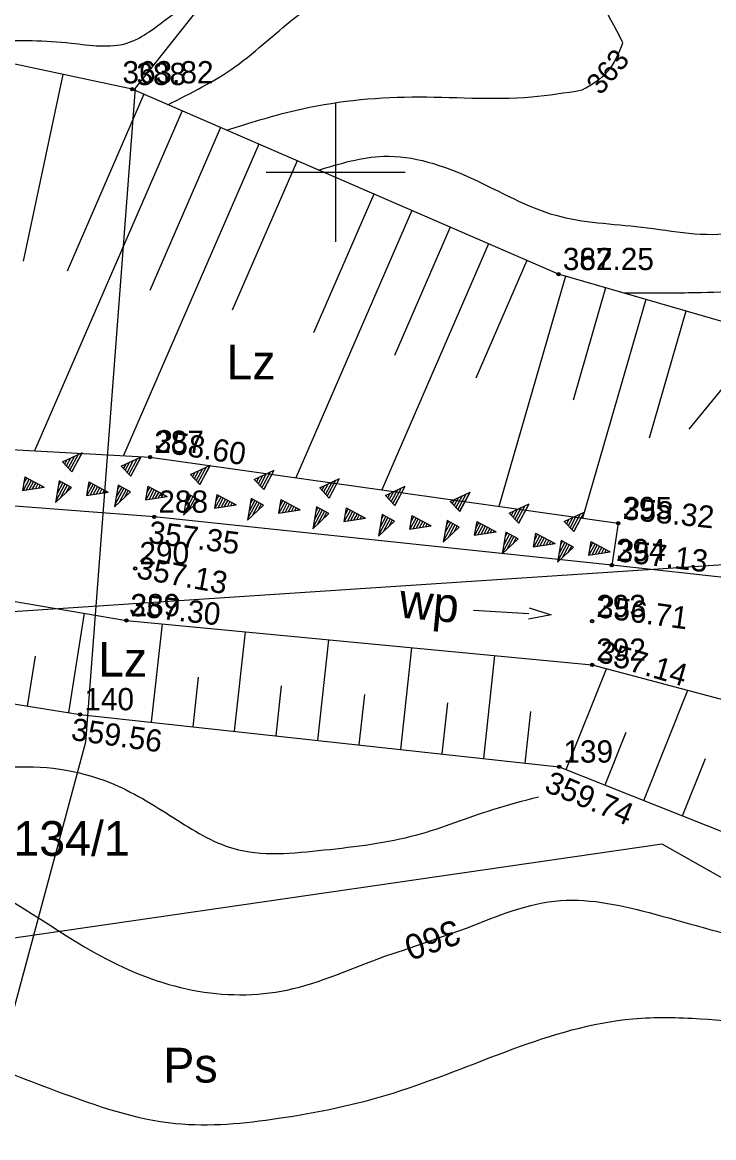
# Model space of a CAD drawing. Extents: x 4635329 to 4651863, y 5356628 to 5367582.
# Drawn here: x 4651688.74 to 4651713.58, y 5357115.3 to 5357155.39 of the extents above; entities that cross this region are included whole.
import ezdxf

# ---------------------------------------------------------------- set-up
doc = ezdxf.new("R2010")
doc.units = 0
for name, color, linetype in [('Level 12', 7, 'Continuous'), ('Level 2', 7, 'Continuous'), ('Level 4', 7, 'Continuous'), ('Level 44', 7, 'Continuous'), ('Level 45', 7, 'Continuous'), ('Level 46', 7, 'Continuous'), ('Level 47', 7, 'Continuous'), ('Level 48', 7, 'Continuous'), ('Level 49', 7, 'Continuous'), ('Level 5', 7, 'Continuous'), ('Level 50', 7, 'Continuous'), ('Level 51', 7, 'Continuous'), ('Level 60', 7, 'Continuous'), ('Level 63', 7, 'Continuous')]:
    doc.layers.add(name, color=color, linetype=linetype)

msp = doc.modelspace()

# ---------------------------------------------------------------- linework, layer by layer
at = {"layer": 'Level 2'}
for p, q in [((4651703.566, 5357166.6), (4651692.792, 5357153.016)), ((4651692.792, 5357153.016), (4651691.014, 5357129.514)), ((4651691.014, 5357129.514), (4651683.746, 5357102.537))]:
    msp.add_line(p, q, dxfattribs=at)
at = {"layer": 'Level 4'}
for p, q in [((4651676.592, 5357133.424), (4651715.978, 5357136.035)), ((4651711.734, 5357125.845), (4651674.589, 5357120.47)), ((4651726.932, 5357117.207), (4651711.734, 5357125.845))]:
    msp.add_line(p, q, dxfattribs=at)
at = {"layer": 'Level 44'}
for centre in [(4651692.69, 5357152.98), (4651708.01, 5357146.33), (4651693.33, 5357139.76), (4651693.48, 5357137.61), (4651710.15, 5357137.38), (4651692.8, 5357135.76), (4651709.92, 5357135.87), (4651692.48, 5357133.89), (4651709.21, 5357133.86), (4651709.21, 5357132.29), (4651690.82, 5357130.51), (4651708.03, 5357128.63)]:
    msp.add_circle(centre, 0.04, dxfattribs=at)
at = {"layer": 'Level 46'}
msp.add_line((4651702.36, 5357122.018), (4651704.704, 5357122.825), dxfattribs=at)
for points in [[(4651693.972, 5357152.424), (4651696.383, 5357153.787), (4651698.687, 5357155.667), (4651700.809, 5357157.244), (4651703.234, 5357162.945), (4651703.477, 5357165.614), (4651703.944, 5357166.275)], [(4651710.321, 5357154.652), (4651708.433, 5357161.075), (4651708.978, 5357163.319), (4651709.008, 5357163.613)], [(4651699.387, 5357150.073), (4651701.719, 5357150.572), (4651704.872, 5357149.784), (4651707.903, 5357148.45), (4651710.995, 5357148.025), (4651714.33, 5357147.843), (4651719.06, 5357153.605), (4651719.242, 5357156.395), (4651719.388, 5357158.154)], [(4651685.635, 5357154.482), (4651687.712, 5357154.697), (4651690.501, 5357154.636), (4651692.502, 5357154.636), (4651693.897, 5357155.485), (4651695.655, 5357157.244), (4651695.684, 5357157.309)], [(4651708.857, 5357152.953), (4651709.767, 5357153.615), (4651710.321, 5357154.652)], [(4651696.082, 5357151.508), (4651698.55, 5357152.22), (4651702.733, 5357152.705), (4651707.038, 5357152.705), (4651708.857, 5357152.953)], [(4651710.298, 5357145.669), (4651712.677, 5357145.669), (4651716.315, 5357145.851), (4651717.767, 5357145.978)], [(4651675.548, 5357131.537), (4651680.727, 5357130.43), (4651683.759, 5357128.489), (4651688.185, 5357128.611), (4651691.883, 5357128.065), (4651694.187, 5357126.791), (4651696.31, 5357125.699), (4651699.584, 5357125.639), (4651702.919, 5357126.184), (4651705.647, 5357127.094), (4651707.29, 5357127.554)], [(4651675.368, 5357129.063), (4651682.425, 5357126.003), (4651686.608, 5357124.729), (4651691.58, 5357121.818), (4651694.854, 5357120.605), (4651698.25, 5357120.605), (4651701.767, 5357121.818), (4651702.36, 5357122.018)], [(4651704.704, 5357122.825), (4651708.072, 5357123.819), (4651711.468, 5357123.334), (4651715.409, 5357122.303), (4651719.593, 5357121.878), (4651722.079, 5357121.939), (4651723.958, 5357122)], [(4651679.579, 5357122.474), (4651681.03, 5357121.575), (4651685.335, 5357118.967), (4651690.004, 5357116.965), (4651694.248, 5357115.813), (4651697.947, 5357115.995), (4651702.07, 5357116.905), (4651710.68, 5357119.573), (4651713.105, 5357119.573), (4651717.471, 5357119.331), (4651721.412, 5357119.998), (4651724.443, 5357120.847), (4651725.213, 5357120.884)]]:
    msp.add_spline(points, degree=3, dxfattribs=at)
at = {"layer": 'Level 48'}
for p, q in [((4651690.203, 5357153.509), (4651688.774, 5357146.798)), ((4651693.109, 5357152.798), (4651690.348, 5357146.436)), ((4651694.485, 5357152.201), (4651689.183, 5357139.986)), ((4651695.861, 5357151.603), (4651693.321, 5357145.751)), ((4651697.237, 5357151.006), (4651692.378, 5357139.812)), ((4651698.613, 5357150.409), (4651696.283, 5357145.041)), ((4651701.365, 5357149.214), (4651699.2, 5357144.225)), ((4651702.741, 5357148.617), (4651698.574, 5357139.018)), ((4651704.117, 5357148.02), (4651702.116, 5357143.41)), ((4651705.493, 5357147.423), (4651701.656, 5357138.582)), ((4651706.869, 5357146.825), (4651705.033, 5357142.595)), ((4651708.256, 5357146.259), (4651705.866, 5357137.986)), ((4651709.697, 5357145.843), (4651708.532, 5357141.808)), ((4651711.138, 5357145.426), (4651708.866, 5357137.562)), ((4651712.579, 5357145.01), (4651711.259, 5357140.439)), ((4651715.426, 5357144.11), (4651712.684, 5357140.76)), ((4651690.41, 5357130.576), (4651690.98, 5357134.146)), ((4651693.389, 5357130.229), (4651693.775, 5357133.766)), ((4651696.371, 5357129.904), (4651696.762, 5357133.481)), ((4651699.354, 5357129.578), (4651699.749, 5357133.195)), ((4651688.928, 5357130.812), (4651689.215, 5357132.606)), ((4651702.336, 5357129.252), (4651702.735, 5357132.909)), ((4651705.318, 5357128.926), (4651705.722, 5357132.623)), ((4651708.283, 5357128.529), (4651709.725, 5357132.153)), ((4651694.88, 5357130.066), (4651695.074, 5357131.845)), ((4651697.862, 5357129.741), (4651698.059, 5357131.539)), ((4651711.07, 5357127.42), (4651712.646, 5357131.379)), ((4651700.845, 5357129.415), (4651701.043, 5357131.233)), ((4651703.827, 5357129.089), (4651704.028, 5357130.928)), ((4651706.809, 5357128.763), (4651707.012, 5357130.622)), ((4651709.676, 5357127.975), (4651710.431, 5357129.87)), ((4651712.464, 5357126.865), (4651713.285, 5357128.928))]:
    msp.add_line(p, q, dxfattribs=at)
for points in [[(4651721.23, 5357139.36), (4651715.28, 5357144.23), (4651708.01, 5357146.33), (4651692.69, 5357152.98), (4651680.43, 5357155.59)], [(4651678.11, 5357140.59), (4651693.33, 5357139.76), (4651710.15, 5357137.38), (4651709.92, 5357135.87)], [(4651678.56, 5357132.47), (4651690.82, 5357130.51), (4651708.03, 5357128.63), (4651714.21, 5357126.17), (4651726.08, 5357121.4), (4651729.4, 5357117.46)]]:
    msp.add_lwpolyline(points, dxfattribs=at)
at = {"layer": 'Level 49'}
for p, q in [((4651690.181, 5357139.588), (4651690.899, 5357139.921)), ((4651690.612, 5357139.788), (4651690.388, 5357139.369)), ((4651690.748, 5357139.851), (4651690.453, 5357139.3)), ((4651690.885, 5357139.914), (4651690.518, 5357139.231)), ((4651690.525, 5357139.224), (4651690.899, 5357139.921)), ((4651692.299, 5357139.437), (4651693.017, 5357139.769)), ((4651692.642, 5357139.073), (4651693.017, 5357139.769)), ((4651690.525, 5357139.224), (4651690.181, 5357139.588)), ((4651690.204, 5357139.598), (4651690.192, 5357139.576)), ((4651690.34, 5357139.661), (4651690.257, 5357139.507)), ((4651690.476, 5357139.725), (4651690.322, 5357139.438)), ((4651692.642, 5357139.073), (4651692.299, 5357139.437)), ((4651692.321, 5357139.447), (4651692.309, 5357139.425)), ((4651692.457, 5357139.51), (4651692.375, 5357139.356)), ((4651692.593, 5357139.573), (4651692.44, 5357139.287)), ((4651692.73, 5357139.636), (4651692.505, 5357139.218)), ((4651692.866, 5357139.7), (4651692.57, 5357139.149)), ((4651693.002, 5357139.763), (4651692.635, 5357139.08)), ((4651694.779, 5357139.134), (4651695.497, 5357139.467)), ((4651695.346, 5357139.397), (4651695.05, 5357138.846)), ((4651695.482, 5357139.46), (4651695.115, 5357138.777)), ((4651695.122, 5357138.77), (4651695.497, 5357139.467)), ((4651688.836, 5357139.052), (4651688.749, 5357138.559)), ((4651688.987, 5357138.971), (4651688.768, 5357138.562)), ((4651688.908, 5357139.013), (4651688.79, 5357138.794)), ((4651688.836, 5357139.052), (4651689.532, 5357138.678)), ((4651695.122, 5357138.77), (4651694.779, 5357139.134)), ((4651694.801, 5357139.145), (4651694.79, 5357139.123)), ((4651694.937, 5357139.208), (4651694.855, 5357139.054)), ((4651695.074, 5357139.271), (4651694.92, 5357138.984)), ((4651695.21, 5357139.334), (4651694.985, 5357138.915)), ((4651697.077, 5357138.952), (4651697.795, 5357139.285)), ((4651697.236, 5357139.026), (4651697.153, 5357138.872)), ((4651697.372, 5357139.089), (4651697.218, 5357138.803)), ((4651697.508, 5357139.152), (4651697.283, 5357138.734)), ((4651697.644, 5357139.216), (4651697.349, 5357138.665)), ((4651697.78, 5357139.279), (4651697.414, 5357138.596)), ((4651697.421, 5357138.589), (4651697.795, 5357139.285)), ((4651699.425, 5357138.652), (4651700.143, 5357138.985)), ((4651700.128, 5357138.978), (4651699.761, 5357138.295)), ((4651699.768, 5357138.288), (4651700.143, 5357138.985)), ((4651688.749, 5357138.559), (4651689.532, 5357138.678)), ((4651689.067, 5357138.928), (4651688.879, 5357138.579)), ((4651689.146, 5357138.885), (4651688.991, 5357138.596)), ((4651689.225, 5357138.843), (4651689.102, 5357138.613)), ((4651689.304, 5357138.8), (4651689.213, 5357138.629)), ((4651689.384, 5357138.758), (4651689.324, 5357138.647)), ((4651689.463, 5357138.715), (4651689.436, 5357138.664)), ((4651690.068, 5357138.902), (4651689.934, 5357138.123)), ((4651689.934, 5357138.123), (4651690.509, 5357138.665)), ((4651690.274, 5357138.791), (4651689.942, 5357138.173)), ((4651690.195, 5357138.834), (4651689.991, 5357138.453)), ((4651690.116, 5357138.876), (4651690.039, 5357138.733)), ((4651690.509, 5357138.665), (4651690.068, 5357138.902)), ((4651690.354, 5357138.748), (4651690.104, 5357138.283)), ((4651690.433, 5357138.706), (4651690.311, 5357138.479)), ((4651691.134, 5357138.87), (4651691.048, 5357138.378)), ((4651691.286, 5357138.789), (4651691.066, 5357138.38)), ((4651691.207, 5357138.832), (4651691.089, 5357138.612)), ((4651691.134, 5357138.87), (4651691.83, 5357138.497)), ((4651691.365, 5357138.747), (4651691.178, 5357138.398)), ((4651691.445, 5357138.704), (4651691.289, 5357138.415)), ((4651691.524, 5357138.661), (4651691.4, 5357138.431)), ((4651691.603, 5357138.619), (4651691.511, 5357138.448)), ((4651691.682, 5357138.576), (4651691.623, 5357138.465)), ((4651692.185, 5357138.75), (4651692.051, 5357137.971)), ((4651692.392, 5357138.64), (4651692.059, 5357138.021)), ((4651692.312, 5357138.682), (4651692.108, 5357138.302)), ((4651692.233, 5357138.725), (4651692.156, 5357138.582)), ((4651692.626, 5357138.514), (4651692.185, 5357138.75)), ((4651692.471, 5357138.597), (4651692.221, 5357138.132)), ((4651693.252, 5357138.719), (4651693.165, 5357138.226)), ((4651693.403, 5357138.638), (4651693.184, 5357138.229)), ((4651693.324, 5357138.68), (4651693.206, 5357138.461)), ((4651693.252, 5357138.719), (4651693.948, 5357138.345)), ((4651693.482, 5357138.595), (4651693.295, 5357138.246)), ((4651697.421, 5357138.589), (4651697.077, 5357138.952)), ((4651697.1, 5357138.963), (4651697.088, 5357138.941)), ((4651699.768, 5357138.288), (4651699.425, 5357138.652)), ((4651699.447, 5357138.662), (4651699.436, 5357138.64)), ((4651699.583, 5357138.725), (4651699.501, 5357138.571)), ((4651699.72, 5357138.788), (4651699.566, 5357138.502)), ((4651699.856, 5357138.852), (4651699.631, 5357138.433)), ((4651699.992, 5357138.915), (4651699.696, 5357138.364)), ((4651701.784, 5357138.379), (4651702.502, 5357138.712)), ((4651702.215, 5357138.579), (4651701.99, 5357138.161)), ((4651702.351, 5357138.642), (4651702.055, 5357138.092)), ((4651702.487, 5357138.706), (4651702.12, 5357138.023)), ((4651702.128, 5357138.015), (4651702.502, 5357138.712)), ((4651691.048, 5357138.378), (4651691.83, 5357138.497)), ((4651691.762, 5357138.534), (4651691.734, 5357138.482)), ((4651692.051, 5357137.971), (4651692.626, 5357138.514)), ((4651692.55, 5357138.555), (4651692.428, 5357138.327)), ((4651693.165, 5357138.226), (4651693.948, 5357138.345)), ((4651693.562, 5357138.553), (4651693.407, 5357138.264)), ((4651693.641, 5357138.51), (4651693.517, 5357138.28)), ((4651693.72, 5357138.467), (4651693.628, 5357138.297)), ((4651693.8, 5357138.425), (4651693.74, 5357138.314)), ((4651693.879, 5357138.382), (4651693.851, 5357138.331)), ((4651694.666, 5357138.448), (4651694.531, 5357137.669)), ((4651694.531, 5357137.669), (4651695.106, 5357138.211)), ((4651694.872, 5357138.337), (4651694.54, 5357137.719)), ((4651694.792, 5357138.38), (4651694.588, 5357137.999)), ((4651694.713, 5357138.422), (4651694.636, 5357138.28)), ((4651695.106, 5357138.211), (4651694.666, 5357138.448)), ((4651694.951, 5357138.295), (4651694.701, 5357137.829)), ((4651695.03, 5357138.252), (4651694.908, 5357138.025)), ((4651695.732, 5357138.417), (4651695.645, 5357137.924)), ((4651695.883, 5357138.335), (4651695.664, 5357137.927)), ((4651695.804, 5357138.378), (4651695.686, 5357138.159)), ((4651695.732, 5357138.417), (4651696.428, 5357138.043)), ((4651695.963, 5357138.293), (4651695.775, 5357137.944)), ((4651696.042, 5357138.25), (4651695.887, 5357137.961)), ((4651696.121, 5357138.208), (4651695.998, 5357137.978)), ((4651696.2, 5357138.165), (4651696.109, 5357137.994)), ((4651696.964, 5357138.266), (4651696.83, 5357137.487)), ((4651697.091, 5357138.198), (4651696.887, 5357137.818)), ((4651697.012, 5357138.241), (4651696.935, 5357138.098)), ((4651697.405, 5357138.03), (4651696.964, 5357138.266)), ((4651698.03, 5357138.235), (4651697.944, 5357137.742)), ((4651698.103, 5357138.196), (4651697.985, 5357137.977)), ((4651698.03, 5357138.235), (4651698.726, 5357137.861)), ((4651702.128, 5357138.015), (4651701.784, 5357138.379)), ((4651701.807, 5357138.39), (4651701.795, 5357138.368)), ((4651701.943, 5357138.453), (4651701.86, 5357138.299)), ((4651702.079, 5357138.516), (4651701.925, 5357138.23)), ((4651704.113, 5357138.168), (4651704.831, 5357138.5)), ((4651704.456, 5357137.804), (4651704.113, 5357138.168)), ((4651704.135, 5357138.178), (4651704.124, 5357138.156)), ((4651704.272, 5357138.241), (4651704.189, 5357138.087)), ((4651704.408, 5357138.304), (4651704.254, 5357138.018)), ((4651704.544, 5357138.368), (4651704.319, 5357137.949)), ((4651704.68, 5357138.431), (4651704.384, 5357137.88)), ((4651704.816, 5357138.494), (4651704.449, 5357137.811)), ((4651704.456, 5357137.804), (4651704.831, 5357138.5)), ((4651695.645, 5357137.924), (4651696.428, 5357138.043)), ((4651696.28, 5357138.122), (4651696.22, 5357138.011)), ((4651696.359, 5357138.08), (4651696.332, 5357138.029)), ((4651696.83, 5357137.487), (4651697.405, 5357138.03)), ((4651697.17, 5357138.156), (4651696.838, 5357137.537)), ((4651697.25, 5357138.113), (4651697, 5357137.648)), ((4651697.329, 5357138.07), (4651697.207, 5357137.843)), ((4651697.944, 5357137.742), (4651698.726, 5357137.861)), ((4651698.182, 5357138.154), (4651697.962, 5357137.745)), ((4651698.261, 5357138.111), (4651698.074, 5357137.762)), ((4651698.34, 5357138.069), (4651698.185, 5357137.78)), ((4651698.42, 5357138.026), (4651698.296, 5357137.796)), ((4651698.499, 5357137.983), (4651698.407, 5357137.812)), ((4651698.578, 5357137.941), (4651698.519, 5357137.83)), ((4651698.658, 5357137.898), (4651698.63, 5357137.847)), ((4651699.312, 5357137.966), (4651699.177, 5357137.187)), ((4651699.518, 5357137.855), (4651699.186, 5357137.236)), ((4651699.438, 5357137.897), (4651699.234, 5357137.517)), ((4651699.359, 5357137.94), (4651699.282, 5357137.797)), ((4651699.752, 5357137.729), (4651699.312, 5357137.966)), ((4651699.597, 5357137.812), (4651699.347, 5357137.347)), ((4651699.676, 5357137.77), (4651699.554, 5357137.542)), ((4651700.378, 5357137.934), (4651700.291, 5357137.442)), ((4651700.529, 5357137.853), (4651700.31, 5357137.444)), ((4651700.45, 5357137.896), (4651700.332, 5357137.676)), ((4651700.378, 5357137.934), (4651701.074, 5357137.56)), ((4651700.609, 5357137.81), (4651700.421, 5357137.461)), ((4651700.688, 5357137.768), (4651700.533, 5357137.479)), ((4651706.23, 5357137.744), (4651706.948, 5357138.077)), ((4651706.389, 5357137.818), (4651706.306, 5357137.664)), ((4651706.525, 5357137.881), (4651706.371, 5357137.595)), ((4651706.661, 5357137.944), (4651706.436, 5357137.525)), ((4651706.797, 5357138.007), (4651706.501, 5357137.456)), ((4651706.933, 5357138.07), (4651706.566, 5357137.387)), ((4651706.574, 5357137.38), (4651706.948, 5357138.077)), ((4651708.214, 5357137.444), (4651708.932, 5357137.776)), ((4651708.917, 5357137.77), (4651708.551, 5357137.087)), ((4651708.558, 5357137.08), (4651708.932, 5357137.776)), ((4651699.177, 5357137.187), (4651699.752, 5357137.729)), ((4651700.291, 5357137.442), (4651701.074, 5357137.56)), ((4651700.767, 5357137.725), (4651700.644, 5357137.495)), ((4651700.846, 5357137.683), (4651700.755, 5357137.512)), ((4651700.926, 5357137.64), (4651700.866, 5357137.529)), ((4651701.005, 5357137.597), (4651700.978, 5357137.546)), ((4651701.671, 5357137.693), (4651701.536, 5357136.914)), ((4651701.536, 5357136.914), (4651702.111, 5357137.457)), ((4651701.877, 5357137.583), (4651701.545, 5357136.964)), ((4651701.798, 5357137.625), (4651701.593, 5357137.245)), ((4651701.718, 5357137.668), (4651701.642, 5357137.525)), ((4651702.111, 5357137.457), (4651701.671, 5357137.693)), ((4651701.956, 5357137.54), (4651701.706, 5357137.075)), ((4651702.035, 5357137.497), (4651701.913, 5357137.27)), ((4651702.737, 5357137.662), (4651702.65, 5357137.169)), ((4651702.888, 5357137.581), (4651702.669, 5357137.172)), ((4651702.809, 5357137.623), (4651702.691, 5357137.404)), ((4651702.737, 5357137.662), (4651703.433, 5357137.288)), ((4651702.968, 5357137.538), (4651702.78, 5357137.189)), ((4651703.047, 5357137.495), (4651702.892, 5357137.207)), ((4651703.126, 5357137.453), (4651703.003, 5357137.223)), ((4651703.206, 5357137.41), (4651703.114, 5357137.239)), ((4651703.285, 5357137.368), (4651703.225, 5357137.257)), ((4651704, 5357137.481), (4651703.865, 5357136.702)), ((4651704.206, 5357137.371), (4651703.874, 5357136.752)), ((4651704.126, 5357137.413), (4651703.922, 5357137.033)), ((4651704.047, 5357137.456), (4651703.971, 5357137.313)), ((4651704.44, 5357137.245), (4651704, 5357137.481)), ((4651705.066, 5357137.45), (4651704.979, 5357136.958)), ((4651705.217, 5357137.369), (4651704.998, 5357136.96)), ((4651705.138, 5357137.411), (4651705.02, 5357137.192)), ((4651705.066, 5357137.45), (4651705.762, 5357137.076)), ((4651706.574, 5357137.38), (4651706.23, 5357137.744)), ((4651706.253, 5357137.755), (4651706.241, 5357137.733)), ((4651708.558, 5357137.08), (4651708.214, 5357137.444)), ((4651708.237, 5357137.454), (4651708.225, 5357137.432)), ((4651708.373, 5357137.517), (4651708.29, 5357137.363)), ((4651708.509, 5357137.58), (4651708.355, 5357137.294)), ((4651708.645, 5357137.643), (4651708.42, 5357137.225)), ((4651708.781, 5357137.707), (4651708.486, 5357137.156)), ((4651702.65, 5357137.169), (4651703.433, 5357137.288)), ((4651703.364, 5357137.325), (4651703.337, 5357137.274)), ((4651703.865, 5357136.702), (4651704.44, 5357137.245)), ((4651704.285, 5357137.328), (4651704.035, 5357136.863)), ((4651704.364, 5357137.286), (4651704.242, 5357137.058)), ((4651704.979, 5357136.958), (4651705.762, 5357137.076)), ((4651705.297, 5357137.326), (4651705.109, 5357136.977)), ((4651705.376, 5357137.284), (4651705.221, 5357136.995)), ((4651705.455, 5357137.241), (4651705.332, 5357137.011)), ((4651705.534, 5357137.199), (4651705.443, 5357137.028)), ((4651705.614, 5357137.156), (4651705.554, 5357137.045)), ((4651705.693, 5357137.113), (4651705.666, 5357137.062)), ((4651706.117, 5357137.058), (4651705.982, 5357136.279)), ((4651706.244, 5357136.99), (4651706.039, 5357136.609)), ((4651706.164, 5357137.032), (4651706.088, 5357136.89)), ((4651706.557, 5357136.821), (4651706.117, 5357137.058)), ((4651707.183, 5357137.027), (4651707.096, 5357136.534)), ((4651707.255, 5357136.988), (4651707.137, 5357136.769)), ((4651707.183, 5357137.027), (4651707.879, 5357136.653)), ((4651705.982, 5357136.279), (4651706.557, 5357136.821)), ((4651706.323, 5357136.947), (4651705.991, 5357136.329)), ((4651706.402, 5357136.905), (4651706.152, 5357136.439)), ((4651706.481, 5357136.862), (4651706.359, 5357136.635)), ((4651707.096, 5357136.534), (4651707.879, 5357136.653)), ((4651707.334, 5357136.945), (4651707.115, 5357136.537)), ((4651707.414, 5357136.903), (4651707.226, 5357136.554)), ((4651707.493, 5357136.86), (4651707.338, 5357136.571)), ((4651707.572, 5357136.818), (4651707.449, 5357136.588)), ((4651707.652, 5357136.775), (4651707.56, 5357136.604)), ((4651707.731, 5357136.732), (4651707.671, 5357136.621)), ((4651707.81, 5357136.69), (4651707.783, 5357136.639)), ((4651708.101, 5357136.757), (4651707.967, 5357135.978)), ((4651708.307, 5357136.647), (4651707.975, 5357136.028)), ((4651708.228, 5357136.689), (4651708.024, 5357136.309)), ((4651708.149, 5357136.732), (4651708.072, 5357136.589)), ((4651708.542, 5357136.521), (4651708.101, 5357136.757)), ((4651708.387, 5357136.604), (4651708.137, 5357136.139)), ((4651708.466, 5357136.561), (4651708.344, 5357136.334)), ((4651709.167, 5357136.726), (4651709.081, 5357136.233)), ((4651709.319, 5357136.645), (4651709.099, 5357136.236)), ((4651709.24, 5357136.687), (4651709.122, 5357136.468)), ((4651709.167, 5357136.726), (4651709.863, 5357136.352)), ((4651709.398, 5357136.602), (4651709.211, 5357136.253)), ((4651707.967, 5357135.978), (4651708.542, 5357136.521)), ((4651709.081, 5357136.233), (4651709.863, 5357136.352)), ((4651709.477, 5357136.56), (4651709.322, 5357136.271)), ((4651709.557, 5357136.517), (4651709.433, 5357136.287)), ((4651709.636, 5357136.474), (4651709.544, 5357136.303)), ((4651709.715, 5357136.432), (4651709.656, 5357136.321)), ((4651709.795, 5357136.389), (4651709.767, 5357136.338))]:
    msp.add_line(p, q, dxfattribs=at)
at = {"layer": 'Level 50'}
for p, q in [((4651693.48, 5357137.61), (4651678.92, 5357138.74)), ((4651709.92, 5357135.87), (4651693.48, 5357137.61)), ((4651678.74, 5357136.24), (4651692.48, 5357133.89)), ((4651717.93, 5357134.99), (4651709.92, 5357135.87)), ((4651704.947, 5357134.262), (4651706.943, 5357134.138)), ((4651706.956, 5357134.338), (4651707.742, 5357134.088)), ((4651692.48, 5357133.89), (4651709.21, 5357132.29)), ((4651707.742, 5357134.088), (4651706.931, 5357133.938)), ((4651709.21, 5357132.29), (4651716.26, 5357130.42))]:
    msp.add_line(p, q, dxfattribs=at)
at = {"layer": 'Level 60'}
for p, q in [((4651700, 5357147.5), (4651700, 5357152.5)), ((4651697.5, 5357150), (4651702.5, 5357150))]:
    msp.add_line(p, q, dxfattribs=at)
at = {"layer": 'Level 63'}
for centre in [(4651692.69, 5357152.98), (4651708.01, 5357146.33), (4651693.33, 5357139.76), (4651693.48, 5357137.61), (4651710.15, 5357137.38), (4651692.8, 5357135.76), (4651709.92, 5357135.87), (4651692.48, 5357133.89), (4651709.21, 5357133.86), (4651709.21, 5357132.29), (4651690.82, 5357130.51), (4651708.03, 5357128.63)]:
    msp.add_circle(centre, 0.06, dxfattribs=at)

# ---------------------------------------------------------------- texts
at = {"layer": 'Level 12'}
for s, p in [('Lz', (4651696.076, 5357142.55)), ('Lz', (4651691.462, 5357131.868)), ('Ps', (4651693.809, 5357117.281))]:
    msp.add_text(s, height=1.25, dxfattribs=at).set_placement(p)
at = {"layer": 'Level 45'}
for s, p in [('363.82', (4651692.339, 5357153.191)), ('362.25', (4651708.16, 5357146.48))]:
    msp.add_text(s, height=0.8, dxfattribs=at).set_placement(p)
for s, rotation, p in [('358.60', 350.8917, (4651693.471, 5357139.982)), ('358.32', 354.1642, (4651710.298, 5357137.527)), ('357.35', 352.5922, (4651693.24, 5357136.681)), ('357.13', 352.8899, (4651710.068, 5357136.02)), ('357.13', 349.681, (4651692.809, 5357135.414)), ('357.30', 353.617, (4651692.561, 5357134.071)), ('356.71', 352.1568, (4651709.357, 5357134.012)), ('357.14', 343.6861, (4651709.348, 5357132.428)), ('359.56', 351.9748, (4651690.463, 5357129.598)), ('359.74', 337.3911, (4651707.455, 5357127.764))]:
    msp.add_text(s, height=0.8, rotation=rotation, dxfattribs=at).set_placement(p)
at = {"layer": 'Level 47'}
for s, height, rotation, p in [('363', 0.75, 49.8076, (4651709.515, 5357152.736)), ('360', 0.9, 199.1156, (4651704.285, 5357123.159))]:
    msp.add_text(s, height=height, rotation=rotation, dxfattribs=at).set_placement(p)
at = {"layer": 'Level 5'}
msp.add_text('134/1', height=1.25, dxfattribs=at).set_placement((4651688.42, 5357125.429))
at = {"layer": 'Level 51'}
msp.add_text('wp', height=1.25, rotation=354.537, dxfattribs=at).set_placement((4651702.244, 5357134))
at = {"layer": 'Level 63'}
for s, p in [('388', (4651692.84, 5357153.13)), ('387', (4651708.16, 5357146.48)), ('287', (4651693.48, 5357139.91)), ('288', (4651693.63, 5357137.76)), ('295', (4651710.3, 5357137.53)), ('290', (4651692.95, 5357135.91)), ('294', (4651710.07, 5357136.02)), ('289', (4651692.63, 5357134.04)), ('293', (4651709.36, 5357134.01)), ('292', (4651709.36, 5357132.44)), ('140', (4651690.97, 5357130.66)), ('139', (4651708.18, 5357128.78))]:
    msp.add_text(s, height=0.8, dxfattribs=at).set_placement(p)

doc.saveas('drawing.dxf')
